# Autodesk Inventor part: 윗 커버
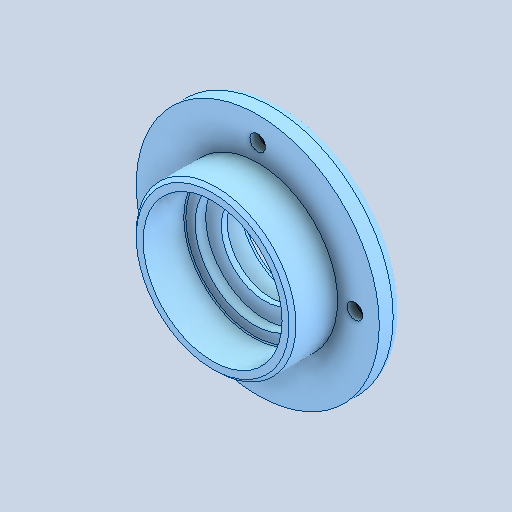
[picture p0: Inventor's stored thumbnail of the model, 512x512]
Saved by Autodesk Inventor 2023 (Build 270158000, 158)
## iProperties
Created: 2025-04
Part Number: 윗 커버
Material: 알루미늄 6061
Document SubType Name: Modeling
Designer: Admin
Density: 2.71 g/cm^3
Appearance: 기본값
Company: 한국ATC센터
Author: jhkim
Revision Number: 1
Sending System: Autodesk Inventor 2026
Preprocessor: ST-DEVELOPER v20.1
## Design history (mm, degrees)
feature "솔리드1"
node "솔리드2"
